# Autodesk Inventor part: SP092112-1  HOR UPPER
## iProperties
Created: 2012-09
Part Number: SP092112-1  HOR UPPER
Material: Aluminum-6061
Description: PROFILE 45X90 UL
Document SubType Name: Modeling
Designer: Administrator
Stock Number: 20.1067 PROFILE 45X90 UL
Density: 2.71 g/cm^3
Mass: 5787.92 g
Surface Area: 23453.6 cm^2
Volume: 2135.76 cm^3
FINISH: CLEAR ANODIZED
Author: Administrator
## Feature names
1. Extrusion1
